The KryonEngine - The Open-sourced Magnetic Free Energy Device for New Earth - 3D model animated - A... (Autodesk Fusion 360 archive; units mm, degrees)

design "Kryon_assy" references "magnet", "Stator-center", "stator", "rotating"
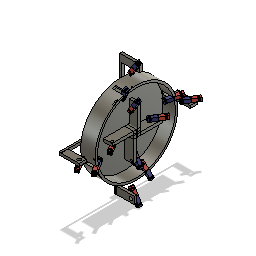
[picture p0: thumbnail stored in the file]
component_insert "Component Insert1"
component_insert "Component Insert2"
component_insert "Component Insert3"
component_insert "Component Insert4"
component_insert "Component Insert5"
joint "Assemble1" alignAngle -90 alignOffsetX 0 alignOffsetY 0 alignOffsetZ 0
joint "Assemble2" alignAngle 0 alignOffsetX 0 alignOffsetY 0 alignOffsetZ 0
joint "Assemble3" alignAngle -270 alignOffsetX 0 alignOffsetY 0 alignOffsetZ 0
joint "Assemble4" alignAngle 180 alignOffsetX 0 alignOffsetY 0 alignOffsetZ 0
component_insert "Component Insert6"
ground "Ground1"
joint "Assemble5" alignAngle 0 alignOffsetX 0 alignOffsetY 0 alignOffsetZ 0
component_insert "Component Insert7"
joint "Assemble6" alignAngle 180 alignOffsetX -35.6542 alignOffsetY -12.841 alignOffsetZ 77.1087
component_insert "Component Insert8"
component_insert "Component Insert9"
component_insert "Component Insert10"
component_insert "Component Insert11"
joint "Assemble7" alignAngle 180 alignOffsetX 0 alignOffsetY 0 alignOffsetZ 0
joint "Assemble8" alignAngle 90 alignOffsetX 0 alignOffsetY 0 alignOffsetZ 0
joint "Assemble9" alignAngle 180 alignOffsetX 0 alignOffsetY 0 alignOffsetZ 0
joint "Assemble10" alignAngle -90 alignOffsetX 0 alignOffsetY 0 alignOffsetZ 0
ground "Ground2"
component_insert "Component Insert12"
component_insert "Component Insert13"
component_insert "Component Insert14"
component_insert "Component Insert15"
joint "Assemble11" alignAngle 90 alignOffsetX 0 alignOffsetY 0 alignOffsetZ 0
joint "Assemble12" alignAngle 90 alignOffsetX 0 alignOffsetY 0 alignOffsetZ 0
joint "Assemble13" alignAngle -90 alignOffsetX 0 alignOffsetY 0 alignOffsetZ 0
joint "Assemble14" alignAngle -90 alignOffsetX 0 alignOffsetY 0 alignOffsetZ 0
ground "Ground3"
position "Position1" RotateAboutZ 180 RotateAboutZ 180 RotateAboutZ 45 RotateAboutZ 180 RotateAboutZ 180 RotateAboutZ 180 RotateAboutZ 180 RotateAboutZ 180
motion_link "MotionLink1" Value1 360 Value2 360
position "Position2"
motion_link "MotionLink2" Value1 360 Value2 360
position "Position3"
motion_link "MotionLink3" Value1 360 Value2 360
position "Position4"
motion_link "MotionLink4" Value1 360 Value2 360
motion_link "MotionLink5" Value1 360 Value2 360
motion_link "MotionLink6" Value1 360 Value2 360
motion_link "MotionLink7" Value1 360 Value2 360
motion_link "MotionLink8" Value1 360 Value2 360
motion_link "MotionLink9" Value1 360 Value2 360
motion_link "MotionLink10" Value1 360 Value2 360
motion_link "MotionLink11" Value1 90 Value2 360
position "Position5" RotateAboutZ 0
motion_link "MotionLink12" Value1 180 Value2 360

design "stator"
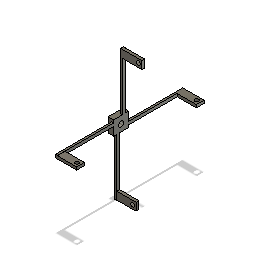
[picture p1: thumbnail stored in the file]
sketch "Sketch1" plane through (0, 0, 0) normal (1, 0, 0) x axis (0, 0, -1)
  line L1 (32.7215, 31.3574) -> (-31.8081, 31.3574)
  line L2 (32.7215, -29.5926) -> (32.7215, 31.3574)
  line L3 (-31.8081, -29.5926) -> (32.7215, -29.5926)
  line L4 (-31.8081, 31.3574) -> (-31.8081, -29.5926)
  circle C1 centre (0, 0) radius 10.5554
  point P1 (0, 0)
  point P2 (0, 0)
  coincident P1 P2
  horizontal L1
  vertical L2
  horizontal L3
  vertical L4
extrude "Extrude1" new body sketch "Sketch1" against normal blind 23.426
sketch "Sketch2" plane through (0, 0, 0) normal (1, 0, 0) x axis (0, 0, -1)
  line L1 (273.7324, -6.625) -> (29.3381, -6.625)
  line L2 (273.7324, -19.6383) -> (273.7324, -6.625)
  line L3 (29.3381, -19.6383) -> (273.7324, -19.6383)
  line L4 (29.3381, -6.625) -> (29.3381, -19.6383)
  horizontal L1
  vertical L2
  horizontal L3
  vertical L4
extrude "Extrude2" add sketch "Sketch2" against normal blind 8.586
sketch "Sketch3" plane through (0, -6.625, 0) normal (0, 1, 0) x axis (-1, 0, 0)
  line L1 (0, -32.7215) -> (8.586, -32.7215)
  line L2 (0, -273.7324) -> (0, -32.7215)
  line L3 (8.586, -273.7324) -> (0, -273.7324)
  line L4 (8.586, -32.7215) -> (8.586, -273.7324)
  line L5 (-83.2503, -273.7324) -> (8.586, -273.7324)
  line L6 (-83.2503, -240.509) -> (-83.2503, -273.7324)
  line L7 (8.586, -240.509) -> (-83.2503, -240.509)
  line L8 (8.586, -273.7324) -> (8.586, -240.509)
  circle C1 centre (-68.0245, -257.5299) radius 8.1172
  point P5 (8.586, -273.7324)
  point P6 (8.586, -273.7324)
  horizontal L5
  vertical L6
  horizontal L7
  vertical L8
  coincident P5 P6
extrude "Extrude3" add sketch "Sketch3" profile of L4 L5 L6 L7 L8 C1 against normal blind 12.132
circular_pattern "C-Pattern1" TotalAngle 360

design "Stator-center"
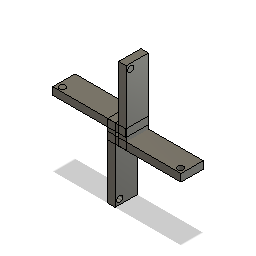
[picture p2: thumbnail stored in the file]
sketch "Sketch1" plane through (0, 0, 0) normal (0, 0, 1) x axis (1, 0, 0)
  line L1 (115.4926, -3.2539) -> (-16.3447, -3.2539)
  line L2 (115.4926, -16.7753) -> (115.4926, -3.2539)
  line L3 (-16.3447, -16.7753) -> (115.4926, -16.7753)
  line L4 (-16.3447, -3.2539) -> (-16.3447, -16.7753)
  horizontal L1
  vertical L2
  horizontal L3
  vertical L4
extrude "Extrude1" new body sketch "Sketch1" along normal blind 40.062
sketch "Sketch2" plane through (0, -3.2539, 0) normal (0, 1, 0) x axis (-1, 0, 0)
  line L1 (16.3447, 0) -> (-115.4926, 0)
  line L2 (16.3447, 40.062) -> (16.3447, 0)
  line L3 (-115.4926, 40.062) -> (16.3447, 40.062)
  line L4 (-115.4926, 0) -> (-115.4926, 40.062)
  circle C1 centre (-106.3592, 31.7487) radius 5.4919
extrude "Extrude2" cut sketch "Sketch2" profile of C1 against normal blind 13.245
circular_pattern "C-Pattern2" TotalAngle 360
circular_pattern "C-Pattern1" TotalAngle 360

design "rotating"
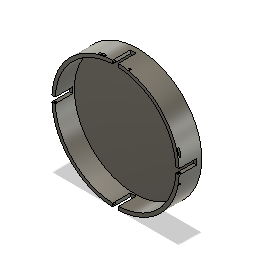
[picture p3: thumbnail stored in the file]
sketch "Sketch1" plane through (0, 0, 0) normal (0, 0, 1) x axis (1, 0, 0)
  circle C1 centre (0, 0) radius 189.9921
  point P1 (0, 0)
  point P2 (0, 0)
  coincident P1 P2
extrude "Extrude1" new body sketch "Sketch1" along normal blind 10
sketch "Sketch2" plane through (0, 0, 0) normal (0, 0, 1) x axis (1, 0, 0)
  circle C1 centre (0, 0) radius 15.9421
  point P1 (0, 0)
  point P2 (0, 0)
  coincident P1 P2
extrude "Extrude2" add sketch "Sketch2" against normal blind 7.2723
sketch "Sketch4" plane through (0, 0, 10) normal (0, 0, 1) x axis (1, 0, 0)
  circle C1 centre (0, 0) radius 189.9921
  circle C2 centre (0, 0) radius 179.9921
  concentric C1 C2
  dimension "d11" distance C1 C2 = 10
extrude "Extrude4" add sketch "Sketch4" along normal blind 57.2418
sketch "Sketch5" plane through (0, 0, 0) normal (1, 0, 0) x axis (0, 0, -1)
  line L1 (-14.6308, 8.4411) -> (-127.1926, 8.4411)
  line L2 (-14.6308, -8.5187) -> (-14.6308, 8.4411)
  line L3 (-127.1926, -8.5187) -> (-14.6308, -8.5187)
  line L4 (-127.1926, 8.4411) -> (-127.1926, -8.5187)
  horizontal L1
  vertical L2
  horizontal L3
  vertical L4
extrude "Extrude5" cut sketch "Sketch5" distance 446.1488
circular_pattern "C-Pattern2" TotalAngle 360
sketch "Sketch6" plane through (0, -8.5187, 0) normal (0, 1, 0) x axis (-1, 0, 0)
  line L1 (189.801, 67.2418) -> (189.801, 14.6308)
  line L2 (179.7904, 67.2418) -> (189.801, 67.2418)
  line L3 (179.7904, 14.6308) -> (179.7904, 67.2418)
  line L4 (189.801, 14.6308) -> (179.7904, 14.6308)
  circle C1 centre (184.1624, 61.816) radius 2.9759
extrude "Extrude6" cut sketch "Sketch6" profile of C1 distance 46.456
circular_pattern "C-Pattern3" TotalAngle 360
sketch "Sketch3" plane through (0, 0, 10) normal (0, 0, 1) x axis (1, 0, 0)
  circle C1 centre (0, 0) radius 69.6137
  circle C2 centre (0, 60) radius 3
  point P1 (0, 0)
  point P3 (0, 60)
  vertical P1 P3
  dimension "d5" diameter C2 = 6
  dimension "d6" distance P1 P3 = 60
extrude "Extrude3" cut sketch "Sketch3" profile of C2 against normal blind 5.722
circular_pattern "C-Pattern1" TotalAngle 360

design "magnet"
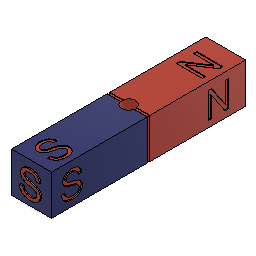
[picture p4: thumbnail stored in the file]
sketch "Sketch1" plane through (0, 0, 0) normal (0, 0, 1) x axis (1, 0, 0)
  line L1 (7.6968, 7.471) -> (-7.6968, 7.471)
  line L2 (7.6968, -7.9225) -> (7.6968, 7.471)
  line L3 (-7.6968, -7.9225) -> (7.6968, -7.9225)
  line L4 (-7.6968, 7.471) -> (-7.6968, -7.9225)
  line L5 (2.6832, 7.471) -> (0, 7.471)
  line L6 (2.6832, -7.9225) -> (2.6832, 7.471)
  line L7 (0, -7.9225) -> (2.6832, -7.9225)
  line L8 (0, 7.471) -> (0, -7.9225)
  point P8 (2.6832, -7.9225)
  point P6 (0, 7.471)
  point P1 (0, 0)
  horizontal L1
  vertical L2
  horizontal L3
  vertical L4
  horizontal L5
  vertical L6
  horizontal L7
  vertical L8
  coincident L3 P8
  midpoint L1 P6
  vertical P1 P6
extrude "Extrude1" new body sketch "Sketch1" distance 37.354
revolve "Revolve1" sketch "Sketch1" AlongAngle 360
sketch "Sketch2" plane through (7.6968, 0, 0) normal (1, 0, 0) x axis (0, 0, -1)
  dimension "d4" = 10
extrude "Extrude2" cut sketch "Sketch2" against normal blind 0.5
circular_pattern "C-Pattern1" TotalAngle 360
sketch "Sketch3" plane through (0, 0, 37.354) normal (0, 0, 1) x axis (1, 0, 0)
  dimension "d9" = 10
extrude "Extrude3" add sketch "Sketch3" along normal blind 0.5
sketch "Sketch4" plane through (0, 0, -37.354) normal (0, 0, -1) x axis (-1, 0, 0)
  dimension "d12" = 10
extrude "Extrude4" cut sketch "Sketch4" against normal blind 0.5
sketch "Sketch5" plane through (0, 0, 0) normal (0, 0, 1) x axis (1, 0, 0)
  line L1 (-7.6968, 7.471) -> (7.6968, 7.471)
  line L2 (-7.6968, -7.9225) -> (-7.6968, 7.471)
  line L3 (7.6968, -7.9225) -> (-7.6968, -7.9225)
  line L4 (7.6968, 7.471) -> (7.6968, -7.9225)
  line L5 (7.4968, 7.271) -> (7.4968, -7.7225)
  line L6 (-7.4968, 7.271) -> (7.4968, 7.271)
  line L7 (-7.4968, -7.7225) -> (-7.4968, 7.271)
  line L8 (7.4968, -7.7225) -> (-7.4968, -7.7225)
  point P3 (-7.6968, -7.9225)
  point P6 (-7.6968, -7.9225)
  point P2 (7.6968, 7.471)
  point P4 (7.6968, 7.471)
  horizontal L1
  vertical L2
  horizontal L3
  vertical L4
  coincident P3 P6
  coincident P2 P4
  dimension "d15" = -0.2
extrude "Extrude5" cut sketch "Sketch5" distance 1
